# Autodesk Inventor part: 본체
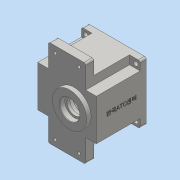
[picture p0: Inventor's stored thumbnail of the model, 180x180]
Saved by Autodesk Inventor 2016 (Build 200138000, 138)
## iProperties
Created: 2020-08
Part Number: 본체
Material: 일반
Document SubType Name: Modeling
Designer: User
Density: 1 g/cm^3
Appearance: 기본값
Mass: 324.733 g
Surface Area: 792.863 cm^2
Volume: 324.733 cm^3
Author: User
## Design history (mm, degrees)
sketch "스케치1"
  geometry: L1 (47, -33)-(-47, -33); L2 (-47, -33)-(-47, 33); L3 (-47, 33)-(47, 33); L4 (47, 33)-(47, -33); L5 (47, -33)-(-47, 33); L6 (-47, -33)-(47, 33); L7 (-30, -70)-(30, -70); L8 (30, -70)-(30, 70); L9 (30, 70)-(-30, 70); L10 (-30, 70)-(-30, -70); L11 (-30, -70)-(30, 70); L12 (30, -70)-(-30, 70); 1 further point
  constraints: 24 end point, 4 midpoint, 4 parallel, 2 horizontal, 2 perpendicular
  dimensions: "d0" = 66 distance of L3.end L1.start; "d1" = 94 distance of L1.start L1.end; "d2" = 60 distance of L7.start L7.end; "d3" = 140 distance of L7.end L8.end
extrude "돌출1" new body sketch "스케치1" distance "d4" = 13; taper "d5" = 0 deg
sketch "스케치2"
  geometry: L1 (-47, 47)-(47, 47); L2 (47, 47)-(47, -47); L3 (47, -47)-(-47, -47); L4 (-47, -47)-(-47, 47); L5 (-47, 47)-(47, -47); L6 (47, 47)-(-47, -47); 1 further point
  constraints: 12 end point, 2 midpoint, 2 parallel, 1 horizontal, 1 perpendicular
  dimensions: "d6" = 94 distance of L2.end L3.end; "d7" = 94 distance of L1.end L2.end
extrude "돌출2" join sketch "스케치2" distance "d8" = 67; taper "d9" = 0 deg
sketch "스케치3"
  geometry: L1 (30, 47)-(30, 33) reference; L2 (30, 33)-(47, 33) reference; L3 (47, 33)-(47, 47) reference; L4 (47, 47)-(30, 47) reference; L5 (-30, 33)-(-30, 47) reference; L6 (-30, 47)-(-47, 47) reference; L7 (-47, 47)-(-47, 33) reference; L8 (-47, 33)-(-30, 33) reference; L9 (-30, -33)-(-47, -33) reference; L10 (-47, -33)-(-47, -47) reference; L11 (-47, -47)-(-30, -47) reference; L12 (-30, -47)-(-30, -33) reference; L13 (47, -33)-(30, -33) reference; L14 (30, -33)-(30, -47) reference; L15 (30, -47)-(47, -47) reference; L16 (47, -47)-(47, -33) reference; 1 further point
extrude "돌출3" cut sketch "스케치3" distance "d10" = 70; taper "d11" = 0 deg
sketch "스케치4"
  geometry: C1 r 27.5 at (11, 0); 1 further point
  constraints: 1 centre point, 1 horizontal alignment
  dimensions: "d12" = 55 diameter of C1; "d13" = 11 distance of point (0, 0) C1.centre
extrude "돌출4" join sketch "스케치4" distance "d14" = 7; taper "d15" = 0 deg
sketch "스케치5"
  geometry: C1 r 43 at (0, 0); 1 further point
  constraints: 1 centre point, 1 coincident
  dimensions: "d16" = 86 diameter of C1
extrude "돌출5" cut sketch "스케치5" distance "d17" = 9; taper "d18" = 0 deg
sketch "스케치6"
  geometry: C1 r 40 at (0, 0); 1 further point
  constraints: 1 centre point, 1 coincident
  dimensions: "d19" = 80 diameter of C1
extrude "돌출6" cut sketch "스케치6" distance "d20" = 62; taper "d21" = 0 deg
sketch "스케치7"
  geometry: C1 r 21 at (11, 0); C2 r 15 at (-20, 0); 1 further point
  constraints: 2 centre point, 2 horizontal alignment
  dimensions: "d22" = 30 diameter of C2; "d23" = 42 diameter of C1; "d24" = 11 distance of point (0, 0) C1.centre; "d25" = 20 distance of point (0, 0) C2.centre
extrude "돌출7" join sketch "스케치7" distance "d26" = 7; taper "d27" = 0 deg
sketch "스케치8"
  geometry: C1 r 16 at (0, 0); A1 r 21 centre (0, 0) between (-18.984, -8.978) and (-18.984, 8.978) reference; 1 further point
  constraints: 1 centre point, 1 coincident
  dimensions: "d28" = 32 diameter of C1
extrude "돌출8" cut sketch "스케치8" distance "d29" = 8.3; taper "d30" = 0 deg
sketch "스케치9"
  geometry: C1 r 16 at (0, 0) reference; C2 r 12.5 at (0, 0); 1 further point
  constraints: 1 centre point, 1 coincident
  dimensions: "d31" = 25 diameter of C2
extrude "돌출9" cut sketch "스케치9" distance "d32" = 4.7; taper "d33" = 0 deg
sketch "스케치10"
  geometry: C1 r 12.5 at (0, 0) reference; C2 r 17.5 at (0, 0); 1 further point
  constraints: 1 centre point, 1 coincident
  dimensions: "d34" = 35 diameter of C2
extrude "돌출10" cut sketch "스케치10" distance "d35" = 10; taper "d36" = 0 deg
sketch "스케치11"
  geometry: C1 r 17.5 at (11, 0) reference; C2 r 11 at (-20, 0); A1 r 21 centre (11, 0) between (-7.984, -8.978) and (-7.984, 8.978) reference; A2 r 15 centre (-20, 0) between (-7.984, 8.978) and (-7.984, -8.978) reference; 1 further point
  constraints: 1 centre point, 1 coincident
  dimensions: "d37" = 22 diameter of C2
extrude "돌출11" cut sketch "스케치11" distance "d38" = 7; taper "d39" = 0 deg
sketch "스케치12"
  geometry: C1 r 11 at (0, 0) reference; C2 r 9.5 at (0, 0); 1 further point
  constraints: 1 centre point, 1 coincident
  dimensions: "d40" = 19 diameter of C2
extrude "돌출12" cut sketch "스케치12" distance "d41" = 3; taper "d42" = 0 deg
sketch "스케치13"
  geometry: A1 r 36 centre (0, 0) between (-3.994, 35.778) and (3.994, 35.778); A2 r 4 centre (0, 36) between (-3.995, 36.19) and (3.995, 36.19); A3 r 3 centre (-6.992, 36.333) between (-4.045, 35.772) and (-7.559, 39.279); A4 r 3 centre (6.992, 36.333) between (7.559, 39.279) and (4.045, 35.772); A5 r 40 centre (0, 0) between (7.559, 39.279) and (-7.559, 39.279) reference; 1 further point
  constraints: 17 point on circle, 4 centre point, 4 tangent, 1 coincident, 1 vertical alignment
  dimensions: "d43" = 72 diameter of A1; "d44" = 8 diameter of A2; "d45" = 6 diameter of A3; "d46" = 6 diameter of A4
extrude "돌출13" join sketch "스케치13" distance "d47" = 62; taper "d48" = 0 deg
sketch "스케치14"
  geometry: C1 r 43 at (0, 0) reference; A1 r 40 centre (0, 0) between (-7.559, 39.279) and (7.559, 39.279) reference; A2 r 3 centre (-6.992, 36.333) between (-3.995, 36.19) and (-7.559, 39.279) reference; A3 r 4 centre (0, 36) between (-3.995, 36.19) and (3.995, 36.19) reference; A4 r 3 centre (6.992, 36.333) between (7.559, 39.279) and (3.995, 36.19) reference; 2 further points
  constraints: 1 coincident
hole "구멍1" sketch "스케치14" at (0, 36) diameter "d49" = 3.242; stored, may be unused: countersink angle "d53" = 90 deg, drill point angle "d55" = 118 deg; dims "d50" = 7, "d51" = 4, "d52" = 2, "d54" = 9
sketch "스케치15"
  geometry: L1 (47, 47)-(-47, 47) reference; L2 (47, -47)-(47, 47) reference; 2 further points
  dimensions: "d56" = 7 distance from line of L1 point (40, 40); "d57" = 7 distance from line of L2 point (40, 40)
hole "구멍2" sketch "스케치15" at (40, 40) diameter "d58" = 7; stored, may be unused: countersink angle "d62" = 90 deg, drill point angle "d64" = 0 deg; dims "d59" = 7, "d60" = 4, "d61" = 2, "d63" = 10
sketch "스케치16"
  geometry: L1 (30, 33)-(30, 70) reference; L2 (30, 70)-(-30, 70) reference; 5 further points
  constraints: 2 horizontal alignment, 2 vertical alignment
  dimensions: "d71" = 11 distance from line of L1 point (19, 60); "d72" = 38 distance of point (-19, 60) point (19, 60); "d73" = 120 distance of point (19, -60) point (19, 60); "d74" = 10 distance from line of L2 point (19, 60)
hole "구멍3" sketch "스케치16" at (19, 60), (-19, 60), (-19, -60), (19, -60) diameter "d75" = 4.5; stored, may be unused: countersink angle "d79" = 90 deg, drill point angle "d81" = 0 deg; dims "d76" = 7, "d77" = 10, "d78" = 5, "d80" = 13
chamfer "모따기1" distance "d82" = 0.8; stored, may be unused: second distance "d83" = 2, angle "d84" = 30 deg
chamfer "모따기2" distance "d85" = 1; stored, may be unused: second distance "d86" = 2, angle "d87" = 30 deg
fillet "모깎기1" dims "d88" = 3
fillet "모깎기3" dims "d90" = 3
fillet "모깎기4" dims "d91" = 3
sketch "스케치17"
  geometry: L1 (-11, 80)-(77, 80) reference; L2 (66, 0)-(0, 0) reference; 3 further points
  constraints: 1 midpoint, 1 vertical alignment, 1 other
  dimensions: "d92" = 40 distance from line of point (33, 40) L1
feature "엠보싱1" sketch "스케치17" dims "d0" = 66, "d1" = 94, "d93" = 0.5, "d94" = 0
fillet "모깎기5" dims "d95" = 3
node "솔리드1"
mirror "대칭1"
pattern_linear "직사각형 패턴1" dims "d67" = 80
node "투영된 루프1"
node "투영된 루프2"
node "투영된 루프3"
node "투영된 루프4"
node "투영된 루프5"
node "투영된 루프6"
node "투영된 루프7"
node "투영된 루프8"
node "투영된 루프9"
